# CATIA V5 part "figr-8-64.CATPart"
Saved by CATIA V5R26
Part number: Part1
Bounding box of the stored display mesh (mm): x -68.924 to 54.237, y -54.052 to 120.856, z 0 to 40
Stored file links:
  D:\_Deepak\CATIA\CATIA V5-6R2016_Deepak\Resources\Part files\Partfiles\c08_catia_v5_6r2016_prt\figr-8-64.CATPart
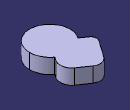
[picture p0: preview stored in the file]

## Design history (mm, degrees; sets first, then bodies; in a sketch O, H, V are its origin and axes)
Body1 (main body)
  Sketch1 on xy-plane, origin (0, 0, 0), H (1, 0, 0), V (0, 1, 0)
    circle A1 centre (0, 0) radius 54.2371
    point P1 (0, 54.2371)
    coincidence: A1 P1, P1 V
  Pad1: profile Sketch1, direction (0, 0, 1), length 40
  Body2
    Sketch2 on xy-plane, origin (0, 0, 0), H (1, 0, 0), V (0, 1, 0)
      line L1 (0, 0) -> (36.9865, 52.8223)
      arc A1 centre (11.6298, 70.5772) radius 30.9549 from (36.9865, 52.8223) to (29.3848, 95.934) ccw
      line L2 (29.3848, 95.934) -> (0.2008, 116.3688)
      arc A2 centre (-14.1853, 95.8234) radius 25.0814 from (0.2008, 116.3688) to (-34.7307, 110.2094) ccw
      line L3 (-34.7307, 110.2094) -> (-66.0893, 65.4248)
      arc A3 centre (-53.2403, 56.4279) radius 15.6856 from (-66.0893, 65.4248) to (-62.2373, 43.579) ccw
      line L4 (-62.2373, 43.579) -> (0, 0)
      tangency: A1 L1, L2 A1, A2 L2, L3 A2, A3 L3, L4 A3
    Pad2: profile Sketch2, direction (0, 0, 1), length 40
  Add1: tool Body2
